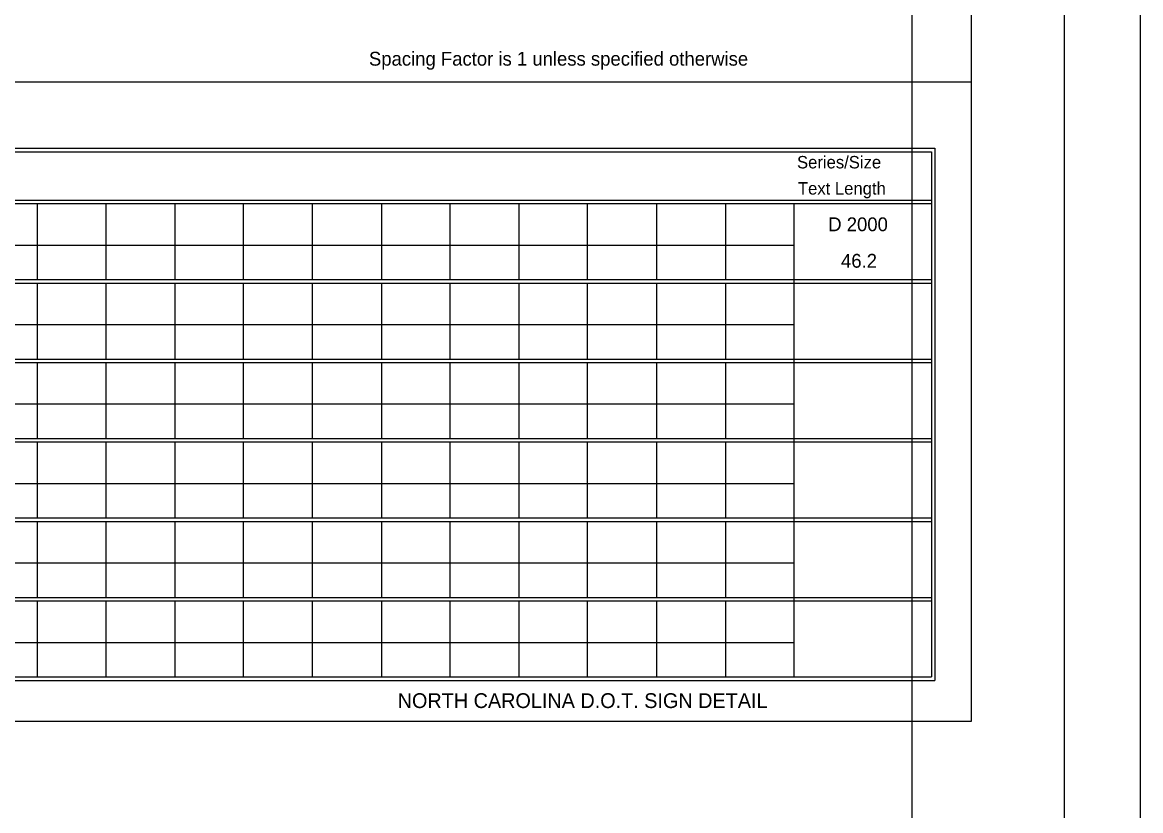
# Model space of a CAD drawing. Extents: x 766449 to 768137, y 650958 to 652521.
# Drawn here: x 767770.1 to 768137.3, y 651739.5 to 651998.5 of the extents above; entities that cross this region are included whole.
import ezdxf

# ---------------------------------------------------------------- set-up
doc = ezdxf.new("R2010")
doc.units = 0
for name, color, linetype in [('DEV BORDER CELL', 7, 'Continuous'), ('Scratch_Level_0', 7, 'Continuous'), ('Sheet Plot Border Outside CELL', 7, 'Continuous'), ('Text', 7, 'Continuous')]:
    doc.layers.add(name, color=color, linetype=linetype)

msp = doc.modelspace()

# ---------------------------------------------------------------- linework, layer by layer
at = {"layer": 'DEV BORDER CELL'}
msp.add_lwpolyline([(768112.34, 652496.28), (766612.34, 652496.28), (766612.34, 651446.28), (768112.34, 651446.28)], close=True, dxfattribs=at)
at = {"layer": 'Scratch_Level_0'}
msp.add_lwpolyline([(768062.34, 652446.28), (766662.34, 652446.28), (766662.34, 651496.28), (767541.19, 651496.28), (767541.19, 651614.55), (768062.34, 651614.55)], close=True, dxfattribs=at)
at = {"layer": 'Sheet Plot Border Outside CELL'}
msp.add_lwpolyline([(766449.34, 651421.28), (768137.34, 651421.28), (768137.34, 652521.28), (766449.34, 652521.28)], close=True, dxfattribs=at)
at = {"layer": 'Text'}
for p, q in [((767657.51, 651978.93), (768081.66, 651978.93)), ((767390.64, 651940.06), (767928.82, 651940.06)), ((767390.64, 651938.93), (767928.82, 651938.93)), ((767775.02, 651938.93), (767775.02, 651913.95)), ((767797.48, 651938.93), (767797.48, 651913.95)), ((767820.17, 651938.93), (767820.17, 651913.95)), ((767842.64, 651938.93), (767842.64, 651913.95)), ((767865.33, 651938.93), (767865.33, 651913.95)), ((767888.02, 651938.93), (767888.02, 651913.95)), ((767904.74, 651940.06), (768068.63, 651940.06)), ((767904.74, 651938.93), (768068.63, 651938.93)), ((767910.48, 651938.93), (767910.48, 651913.95)), ((767910.48, 651938.93), (767910.48, 651913.95)), ((767933.17, 651938.93), (767933.17, 651913.95)), ((767955.64, 651938.93), (767955.64, 651913.95)), ((767978.33, 651938.93), (767978.33, 651913.95)), ((768001.02, 651938.93), (768001.02, 651913.95)), ((768023.48, 651938.93), (768023.48, 651787.58)), ((767413.33, 651925.3), (767928.82, 651925.3)), ((767904.74, 651925.3), (768023.48, 651925.3)), ((768023.48, 651920.13), (768023.48, 651913.95)), ((767390.64, 651913.95), (767928.82, 651913.95)), ((767390.64, 651912.82), (767928.82, 651912.82)), ((767775.02, 651912.82), (767775.02, 651887.85)), ((767797.48, 651912.82), (767797.48, 651887.85)), ((767820.17, 651912.82), (767820.17, 651887.85)), ((767842.64, 651912.82), (767842.64, 651887.85)), ((767865.33, 651912.82), (767865.33, 651887.85)), ((767888.02, 651912.82), (767888.02, 651887.85)), ((767904.74, 651913.95), (768068.63, 651913.95)), ((767904.74, 651912.82), (768068.63, 651912.82)), ((767910.48, 651912.82), (767910.48, 651887.85)), ((767910.48, 651912.82), (767910.48, 651887.85)), ((767933.17, 651912.82), (767933.17, 651887.85)), ((767955.64, 651912.82), (767955.64, 651887.85)), ((767978.33, 651912.82), (767978.33, 651887.85)), ((768001.02, 651912.82), (768001.02, 651887.85)), ((768023.48, 651912.82), (768023.48, 651900.97)), ((767413.33, 651899.2), (767928.82, 651899.2)), ((767904.74, 651899.2), (768023.48, 651899.2)), ((768023.48, 651895.97), (768023.48, 651887.85)), ((767390.64, 651887.85), (767928.82, 651887.85)), ((767390.64, 651886.71), (767928.82, 651886.71)), ((767775.02, 651886.71), (767775.02, 651861.74)), ((767797.48, 651886.71), (767797.48, 651861.74)), ((767820.17, 651886.71), (767820.17, 651861.74)), ((767842.64, 651886.71), (767842.64, 651861.74)), ((767865.33, 651886.71), (767865.33, 651861.74)), ((767888.02, 651886.71), (767888.02, 651861.74)), ((767904.74, 651887.85), (768068.63, 651887.85)), ((767904.74, 651886.71), (768068.63, 651886.71)), ((767910.48, 651886.71), (767910.48, 651861.74)), ((767910.48, 651886.71), (767910.48, 651861.74)), ((767933.17, 651886.71), (767933.17, 651861.74)), ((767955.64, 651886.71), (767955.64, 651861.74)), ((767978.33, 651886.71), (767978.33, 651861.74)), ((768001.02, 651886.71), (768001.02, 651861.74)), ((768023.48, 651886.71), (768023.48, 651876.56)), ((767413.33, 651873.09), (767928.82, 651873.09)), ((767904.74, 651873.09), (768023.48, 651873.09)), ((768023.48, 651869.1), (768023.48, 651861.74)), ((767390.64, 651861.74), (767928.82, 651861.74)), ((767904.74, 651861.74), (768068.63, 651861.74)), ((767390.64, 651860.61), (767928.82, 651860.61)), ((767775.02, 651860.61), (767775.02, 651835.63)), ((767797.48, 651860.61), (767797.48, 651835.63)), ((767820.17, 651860.61), (767820.17, 651835.63)), ((767842.64, 651860.61), (767842.64, 651835.63)), ((767865.33, 651860.61), (767865.33, 651835.63)), ((767888.02, 651860.61), (767888.02, 651835.63)), ((767904.74, 651860.61), (768068.63, 651860.61)), ((767910.48, 651860.61), (767910.48, 651835.63)), ((767910.48, 651860.61), (767910.48, 651835.63)), ((767933.17, 651860.61), (767933.17, 651835.63)), ((767955.64, 651860.61), (767955.64, 651835.63)), ((767978.33, 651860.61), (767978.33, 651835.63)), ((768001.02, 651860.61), (768001.02, 651835.63)), ((768023.48, 651860.61), (768023.48, 651849.66)), ((767413.33, 651846.98), (767928.82, 651846.98)), ((767904.74, 651846.98), (768023.48, 651846.98)), ((768023.48, 651842.19), (768023.48, 651835.63)), ((767390.64, 651835.63), (767928.82, 651835.63)), ((767390.64, 651835.63), (767928.82, 651835.63)), ((767775.02, 651838.54), (767775.02, 651835.63)), ((767797.48, 651838.54), (767797.48, 651835.63)), ((767820.17, 651838.54), (767820.17, 651835.63)), ((767842.64, 651838.54), (767842.64, 651835.63)), ((767865.33, 651838.54), (767865.33, 651835.63)), ((767888.02, 651838.54), (767888.02, 651835.63)), ((767904.74, 651835.63), (768068.63, 651835.63)), ((767904.74, 651835.63), (768068.63, 651835.63)), ((767910.48, 651838.54), (767910.48, 651835.63)), ((767910.48, 651838.54), (767910.48, 651835.63)), ((767933.17, 651838.54), (767933.17, 651835.63)), ((767955.64, 651838.54), (767955.64, 651835.63)), ((767978.33, 651838.54), (767978.33, 651835.63)), ((768001.02, 651838.54), (768001.02, 651835.63)), ((768023.48, 651838.54), (768023.48, 651835.63)), ((767390.64, 651834.5), (767928.82, 651834.5)), ((767390.64, 651834.5), (767928.82, 651834.5)), ((767775.02, 651834.5), (767775.02, 651811.16)), ((767775.02, 651834.5), (767775.02, 651809.53)), ((767797.48, 651834.5), (767797.48, 651811.16)), ((767797.48, 651834.5), (767797.48, 651809.53)), ((767820.17, 651834.5), (767820.17, 651811.16)), ((767820.17, 651834.5), (767820.17, 651809.53)), ((767842.64, 651834.5), (767842.64, 651811.16)), ((767842.64, 651834.5), (767842.64, 651809.53)), ((767865.33, 651834.5), (767865.33, 651811.16)), ((767865.33, 651834.5), (767865.33, 651809.53)), ((767888.02, 651834.5), (767888.02, 651811.16)), ((767888.02, 651834.5), (767888.02, 651809.53)), ((767904.74, 651834.5), (768068.63, 651834.5)), ((767904.74, 651834.5), (768068.63, 651834.5)), ((767910.48, 651834.5), (767910.48, 651811.16)), ((767910.48, 651834.5), (767910.48, 651809.53)), ((767910.48, 651834.5), (767910.48, 651811.16)), ((767910.48, 651834.5), (767910.48, 651809.53)), ((767933.17, 651834.5), (767933.17, 651811.16)), ((767933.17, 651834.5), (767933.17, 651809.53)), ((767955.64, 651834.5), (767955.64, 651811.16)), ((767955.64, 651834.5), (767955.64, 651809.53)), ((767978.33, 651834.5), (767978.33, 651811.16)), ((767978.33, 651834.5), (767978.33, 651809.53)), ((768001.02, 651834.5), (768001.02, 651811.16)), ((768001.02, 651834.5), (768001.02, 651809.53)), ((768023.48, 651834.5), (768023.48, 651823.26)), ((768023.48, 651834.5), (768023.48, 651823.26)), ((767413.33, 651820.88), (767928.82, 651820.88)), ((767413.33, 651820.88), (767928.82, 651820.88)), ((767904.74, 651820.88), (768023.48, 651820.88)), ((767904.74, 651820.88), (768017.6, 651820.88)), ((768023.48, 651816.79), (768023.48, 651811.16)), ((768023.48, 651816.79), (768023.48, 651809.53)), ((767775.02, 651812.43), (767775.02, 651809.53)), ((767797.48, 651812.43), (767797.48, 651809.53)), ((767820.17, 651812.43), (767820.17, 651809.53)), ((767842.64, 651812.43), (767842.64, 651809.53)), ((767865.33, 651812.43), (767865.33, 651809.53)), ((767888.02, 651812.43), (767888.02, 651809.53)), ((767910.48, 651812.43), (767910.48, 651809.53)), ((767910.48, 651812.43), (767910.48, 651809.53)), ((767933.17, 651812.43), (767933.17, 651809.53)), ((767955.64, 651812.43), (767955.64, 651809.53)), ((767978.33, 651812.43), (767978.33, 651809.53)), ((768001.02, 651812.43), (768001.02, 651809.53)), ((768023.48, 651812.43), (768023.48, 651809.53)), ((767390.64, 651809.53), (767928.82, 651809.53)), ((767390.64, 651809.53), (767928.82, 651809.53)), ((767390.64, 651808.39), (767928.82, 651808.39)), ((767390.64, 651808.39), (767928.82, 651808.39)), ((767775.02, 651808.39), (767775.02, 651783.42)), ((767775.02, 651808.39), (767775.02, 651783.42)), ((767797.48, 651808.39), (767797.48, 651783.42)), ((767797.48, 651808.39), (767797.48, 651783.42)), ((767820.17, 651808.39), (767820.17, 651783.42)), ((767820.17, 651808.39), (767820.17, 651783.42)), ((767842.64, 651808.39), (767842.64, 651783.42)), ((767842.64, 651808.39), (767842.64, 651783.42)), ((767865.33, 651808.39), (767865.33, 651783.42)), ((767865.33, 651808.39), (767865.33, 651783.42)), ((767888.02, 651808.39), (767888.02, 651783.42)), ((767888.02, 651808.39), (767888.02, 651783.42)), ((767904.74, 651809.53), (768068.63, 651809.53)), ((767904.74, 651809.53), (768068.63, 651809.53)), ((767904.74, 651808.39), (768068.63, 651808.39)), ((767904.74, 651808.39), (768068.63, 651808.39)), ((767910.48, 651808.39), (767910.48, 651783.42)), ((767910.48, 651808.39), (767910.48, 651783.42)), ((767910.48, 651808.39), (767910.48, 651783.42)), ((767910.48, 651808.39), (767910.48, 651783.42)), ((767933.17, 651808.39), (767933.17, 651783.42)), ((767933.17, 651808.39), (767933.17, 651783.42)), ((767955.64, 651808.39), (767955.64, 651783.42)), ((767955.64, 651808.39), (767955.64, 651783.42)), ((767978.33, 651808.39), (767978.33, 651783.42)), ((767978.33, 651808.39), (767978.33, 651783.42)), ((768001.02, 651808.39), (768001.02, 651783.42)), ((768001.02, 651808.39), (768001.02, 651783.42)), ((768023.48, 651808.39), (768023.48, 651797.88)), ((768023.48, 651808.39), (768023.48, 651797.88)), ((767413.33, 651794.77), (767928.82, 651794.77)), ((767413.33, 651794.77), (767928.82, 651794.77)), ((767904.74, 651794.77), (768023.48, 651794.77)), ((767904.74, 651794.77), (768019.13, 651794.77)), ((768023.48, 651789.91), (768023.48, 651783.42)), ((768023.48, 651789.91), (768023.48, 651783.42)), ((767389.48, 651782.29), (767928.82, 651782.29)), ((767390.64, 651783.42), (767928.82, 651783.42)), ((767390.64, 651783.42), (767928.82, 651783.42)), ((767390.64, 651782.29), (767928.82, 651782.29)), ((767904.74, 651783.42), (768068.63, 651783.42)), ((767904.74, 651783.42), (768068.63, 651783.42)), ((767904.74, 651782.29), (768069.79, 651782.29)), ((767904.74, 651782.29), (768068.63, 651782.29))]:
    msp.add_line(p, q, dxfattribs=at)
msp.add_lwpolyline([(767381.66, 652254.24), (768081.66, 652254.24), (768081.66, 651768.77), (767381.66, 651768.77)], close=True, dxfattribs=at)
for points in [[(767389.48, 651811.16), (767389.48, 651957.09), (767928.82, 651957.09)], [(767904.74, 651957.09), (768069.79, 651957.09), (768069.79, 651811.16)], [(767390.64, 651811.16), (767390.64, 651955.95), (767928.82, 651955.95)], [(767904.74, 651955.95), (768068.63, 651955.95), (768068.63, 651811.16)], [(768068.63, 651838.54), (768068.63, 651783.42)], [(768069.79, 651838.54), (768069.79, 651782.29)]]:
    msp.add_lwpolyline(points, dxfattribs=at)

# ---------------------------------------------------------------- texts
for s, height, p in [('Spacing Factor is 1 unless specified otherwise', 4.5403, (767883.93, 651984.24)), ('Series/Size', 4.0863, (768024.5, 651950.48)), ('Text Length', 4.0863, (768024.8, 651941.88)), ('NORTH CAROLINA D.O.T. SIGN DETAIL', 4.8646, (767893.37, 651773.19))]:
    msp.add_text(s, height=height, rotation=360, dxfattribs=at).set_placement(p)
for s, p in [('D 2000', (768034.76, 651929.85)), ('46.2', (768038.95, 651917.86))]:
    msp.add_text(s, height=4.54, dxfattribs=at).set_placement(p)

doc.saveas('drawing.dxf')
